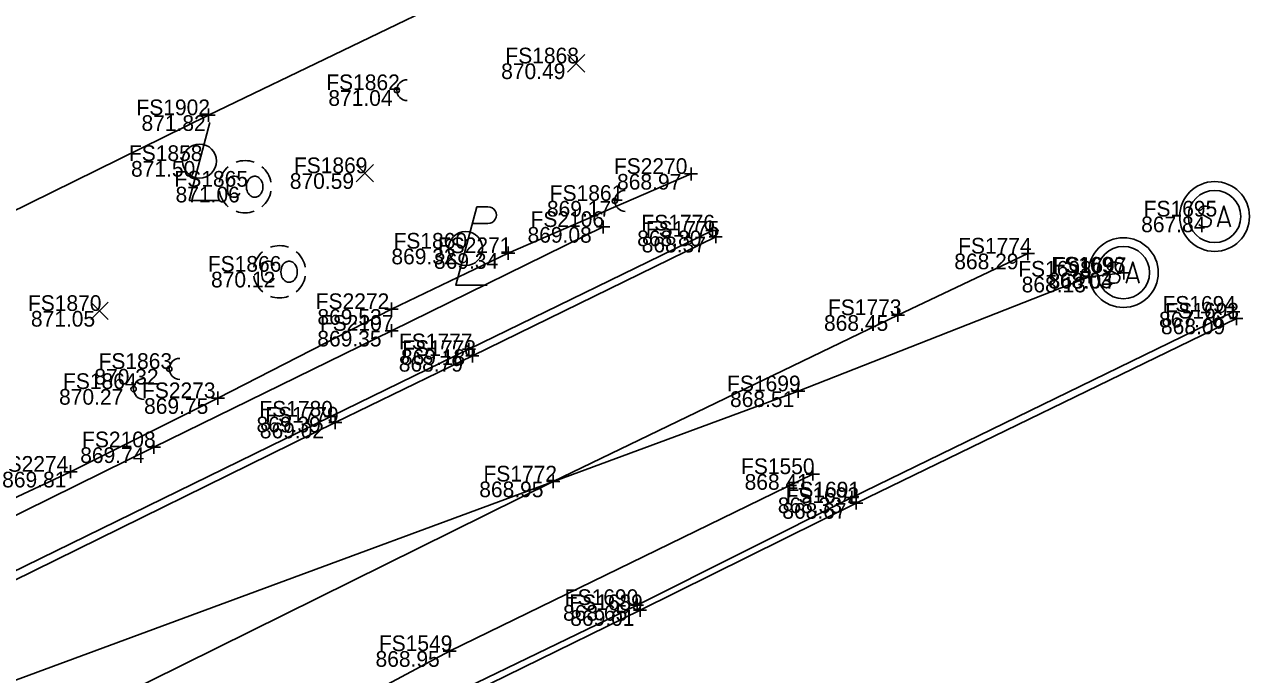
# Model space of a CAD drawing. Extents: x 1479420 to 1479833, y 379731 to 380103.
# Drawn here: x 1479739 to 1479832.6, y 379969.5 to 380019.2 of the extents above; entities that cross this region are included whole.
import ezdxf

# ---------------------------------------------------------------- set-up
doc = ezdxf.new("R2010")
doc.units = 0
for name, color, linetype in [('DR_X_Cells', 7, 'Continuous'), ('GK_Drainage_Nodes', 7, 'Continuous'), ('LT_X_Poles', 7, 'Continuous'), ('PM_X_CL_Double_Solid', 7, 'Continuous'), ('PV_X_Curb', 7, 'Continuous'), ('PV_X_Walk', 7, 'Continuous'), ('SV_X_Random_Point', 7, 'Continuous'), ('SV_X_Shot_Marker', 7, 'Continuous'), ('SV_X_Text_Elevation', 7, 'Continuous'), ('SV_X_Text_Name', 7, 'Continuous'), ('UT_X_Gas', 7, 'Continuous'), ('UT_X_Misc_Cells', 7, 'Continuous'), ('UT_X_Sanitary_Cells', 7, 'Continuous'), ('UT_X_Sanitary_Line', 7, 'Continuous'), ('UT_X_Water', 7, 'Continuous')]:
    doc.layers.add(name, color=color, linetype=linetype)

msp = doc.modelspace()

# ---------------------------------------------------------------- linework, layer by layer
at = {"layer": 'DR_X_Cells'}
for p, q in [((1479755.88, 380006.812), (1479755.88, 380006.812)), ((1479758.507, 380000.311), (1479758.507, 380000.311))]:
    msp.add_line(p, q, dxfattribs=at)
for points in [[(1479755.466, 380007.297), (1479755.403, 380007.435), (1479755.34, 380007.511), (1479755.277, 380007.561), (1479755.226, 380007.587), (1479755.088, 380007.612), (1479754.949, 380007.612), (1479754.773, 380007.561), (1479754.672, 380007.486), (1479754.621, 380007.423), (1479754.571, 380007.335), (1479754.533, 380007.196), (1479754.521, 380006.944), (1479754.521, 380006.755), (1479754.521, 380006.629), (1479754.533, 380006.516), (1479754.571, 380006.314), (1479754.584, 380006.276), (1479754.634, 380006.188), (1479754.685, 380006.125), (1479754.773, 380006.062), (1479754.848, 380006.037), (1479754.949, 380006.012), (1479755.062, 380006.012), (1479755.176, 380006.024), (1479755.214, 380006.037), (1479755.264, 380006.062), (1479755.314, 380006.113), (1479755.377, 380006.176), (1479755.428, 380006.251), (1479755.466, 380006.314)], [(1479756.486, 380007.599), (1479756.448, 380007.587), (1479756.41, 380007.574), (1479756.347, 380007.536), (1479756.31, 380007.511), (1479756.247, 380007.461), (1479756.196, 380007.41), (1479756.171, 380007.385), (1479756.133, 380007.335), (1479756.07, 380007.209), (1479756.02, 380007.083), (1479755.995, 380006.969), (1479755.982, 380006.805), (1479755.995, 380006.629), (1479756.032, 380006.503), (1479756.07, 380006.402), (1479756.095, 380006.352), (1479756.133, 380006.289), (1479756.184, 380006.226), (1479756.221, 380006.188), (1479756.259, 380006.15), (1479756.31, 380006.113), (1479756.373, 380006.075), (1479756.486, 380006.024), (1479756.549, 380006.012), (1479756.675, 380006.012), (1479756.725, 380006.024), (1479756.776, 380006.037), (1479756.839, 380006.062), (1479756.902, 380006.1), (1479756.939, 380006.125), (1479756.977, 380006.15), (1479757.015, 380006.188), (1479757.053, 380006.238), (1479757.078, 380006.276), (1479757.103, 380006.314), (1479757.128, 380006.352), (1479757.166, 380006.428), (1479757.204, 380006.516), (1479757.229, 380006.616), (1479757.242, 380006.705), (1479757.242, 380006.717), (1479757.242, 380006.805), (1479757.242, 380006.881), (1479757.229, 380006.982), (1479757.204, 380007.083), (1479757.179, 380007.158), (1479757.141, 380007.246), (1479757.103, 380007.322), (1479757.04, 380007.397), (1479756.99, 380007.448), (1479756.939, 380007.498), (1479756.889, 380007.536), (1479756.813, 380007.574), (1479756.738, 380007.599), (1479756.662, 380007.612), (1479756.574, 380007.612), (1479756.486, 380007.599)], [(1479758.093, 380000.796), (1479758.03, 380000.934), (1479757.967, 380001.01), (1479757.904, 380001.06), (1479757.853, 380001.085), (1479757.715, 380001.111), (1479757.576, 380001.111), (1479757.4, 380001.06), (1479757.299, 380000.985), (1479757.248, 380000.922), (1479757.198, 380000.833), (1479757.16, 380000.695), (1479757.148, 380000.443), (1479757.148, 380000.254), (1479757.148, 380000.128), (1479757.16, 380000.015), (1479757.198, 379999.813), (1479757.211, 379999.775), (1479757.261, 379999.687), (1479757.312, 379999.624), (1479757.4, 379999.561), (1479757.475, 379999.536), (1479757.576, 379999.511), (1479757.689, 379999.511), (1479757.803, 379999.523), (1479757.841, 379999.536), (1479757.891, 379999.561), (1479757.941, 379999.611), (1479758.004, 379999.674), (1479758.055, 379999.75), (1479758.093, 379999.813)], [(1479759.113, 380001.098), (1479759.075, 380001.085), (1479759.037, 380001.073), (1479758.974, 380001.035), (1479758.937, 380001.01), (1479758.874, 380000.959), (1479758.823, 380000.909), (1479758.798, 380000.884), (1479758.76, 380000.833), (1479758.697, 380000.707), (1479758.647, 380000.582), (1479758.622, 380000.468), (1479758.609, 380000.304), (1479758.622, 380000.128), (1479758.659, 380000.002), (1479758.697, 379999.901), (1479758.722, 379999.851), (1479758.76, 379999.788), (1479758.811, 379999.725), (1479758.848, 379999.687), (1479758.886, 379999.649), (1479758.937, 379999.611), (1479759, 379999.574), (1479759.113, 379999.523), (1479759.176, 379999.511), (1479759.302, 379999.511), (1479759.352, 379999.523), (1479759.403, 379999.536), (1479759.466, 379999.561), (1479759.529, 379999.599), (1479759.566, 379999.624), (1479759.604, 379999.649), (1479759.642, 379999.687), (1479759.68, 379999.737), (1479759.705, 379999.775), (1479759.73, 379999.813), (1479759.755, 379999.851), (1479759.793, 379999.926), (1479759.831, 380000.015), (1479759.856, 380000.115), (1479759.869, 380000.204), (1479759.869, 380000.216), (1479759.869, 380000.304), (1479759.869, 380000.38), (1479759.856, 380000.481), (1479759.831, 380000.582), (1479759.806, 380000.657), (1479759.768, 380000.745), (1479759.73, 380000.821), (1479759.667, 380000.896), (1479759.617, 380000.947), (1479759.566, 380000.997), (1479759.516, 380001.035), (1479759.44, 380001.073), (1479759.365, 380001.098), (1479759.289, 380001.111), (1479759.201, 380001.111), (1479759.113, 380001.098)]]:
    msp.add_lwpolyline(points, dxfattribs=at)
for centre, start, end in [((1479755.879, 380006.81), 70.05767, 110.10608), ((1479755.879, 380006.81), 130.0806, 170.07213), ((1479755.879, 380006.81), 10.01689, 50.03919), ((1479755.879, 380006.81), 190.01689, 230.03919), ((1479755.879, 380006.81), 310.01144, 350.02638), ((1479755.879, 380006.81), 250.05767, 290.04731), ((1479758.506, 380000.309), 70.05767, 110.10608), ((1479758.506, 380000.309), 130.0806, 170.07213), ((1479758.506, 380000.309), 10.01689, 50.03919), ((1479758.506, 380000.309), 190.01689, 230.03919), ((1479758.506, 380000.309), 310.01144, 350.02638), ((1479758.506, 380000.309), 250.05767, 290.04731)]:
    msp.add_arc(centre, 2, start, end, dxfattribs=at)
at = {"layer": 'GK_Drainage_Nodes'}
for p, q in [((1479829.977, 380006.534), (1479829.977, 380006.534)), ((1479829.977, 380004.534), (1479829.977, 380004.534)), ((1479829.977, 380004.534), (1479829.977, 380004.534)), ((1479829.977, 380004.534), (1479829.977, 380004.534)), ((1479823.004, 380002.243), (1479823.004, 380002.243)), ((1479829.977, 380002.534), (1479829.977, 380002.534)), ((1479823.004, 380000.243), (1479823.004, 380000.243)), ((1479823.004, 380000.243), (1479823.004, 380000.243)), ((1479823.004, 380000.243), (1479823.004, 380000.243)), ((1479823.004, 379998.243), (1479823.004, 379998.243))]:
    msp.add_line(p, q, dxfattribs=at)
for centre in [(1479829.977, 380004.534), (1479823.004, 380000.243)]:
    msp.add_circle(centre, 2, dxfattribs=at)
at = {"layer": 'LT_X_Poles'}
msp.add_lwpolyline([(1479753.18, 380011.73), (1479751.605, 380005.745), (1479753.968, 380005.745)], dxfattribs=at)
msp.add_circle((1479752.393, 380008.776), 1.3, dxfattribs=at)
at = {"layer": 'PM_X_CL_Double_Solid'}
msp.add_lwpolyline([(1479687.377, 379938.814), (1479706.5, 379948.023), (1479725.914, 379957.781), (1479746.012, 379967.724), (1479779.432, 379984.272), (1479805.773, 379996.992), (1479815.711, 380001.699)], dxfattribs=at)
at = {"layer": 'PV_X_Curb'}
for points in [[(1479795.994, 380033.189), (1479773.609, 380022.189), (1479753.08, 380012.28), (1479732.582, 380002.187), (1479709.578, 379990.944), (1479686.038, 379979.568), (1479675.424, 379995.638), (1479673.845, 379997.042), (1479672.388, 379997.402), (1479671.072, 379997.477), (1479668.749, 379997.507), (1479666.577, 379997.444), (1479665.261, 379997.435), (1479663.761, 379996.907), (1479662.621, 379996.118), (1479646.813, 379979.589), (1479631.39, 379994.413), (1479612.948, 380012.393), (1479594.615, 380030.048), (1479574.047, 380049.976), (1479559.355, 380064.639), (1479550.33, 380073.358), (1479530.481, 380092.839), (1479523.351, 380099.687)], [(1479791.848, 380002.989), (1479773.254, 379993.873), (1479762.766, 379988.772), (1479738.122, 379976.643), (1479720.845, 379968.214), (1479698.694, 379957.239), (1479678.815, 379947.539), (1479674.951, 379945.56), (1479671.194, 379943.855), (1479668.836, 379942.929), (1479666.481, 379942.243), (1479664.295, 379941.704), (1479662.026, 379941.397), (1479659.994, 379941.512), (1479654.023, 379942.767), (1479648.758, 379945.101), (1479643.81, 379948.553), (1479642.638, 379949.516), (1479640.65, 379951.389), (1479638.379, 379953.495), (1479620.029, 379971.274), (1479601.931, 379988.801), (1479602.178, 379989.373), (1479582.142, 380008.015)], [(1479791.59, 380003.464), (1479772.982, 379994.381), (1479762.438, 379989.23), (1479737.891, 379977.225), (1479720.638, 379968.611), (1479698.71, 379957.883), (1479678.409, 379947.915), (1479674.816, 379946.157), (1479670.835, 379944.353), (1479668.74, 379943.532), (1479666.343, 379942.649), (1479664.179, 379942.195), (1479661.876, 379941.9), (1479659.999, 379941.971), (1479653.935, 379943.268), (1479649.182, 379945.527), (1479644.261, 379948.889), (1479643.432, 379949.993), (1479639.011, 379953.958), (1479638.818, 379953.848), (1479620.557, 379971.482), (1479582.44, 380008.391)], [(1479695.142, 379911.53), (1479695.083, 379915.321), (1479695.466, 379917.321), (1479696.046, 379920.608), (1479697.317, 379923.298), (1479700.059, 379927.556), (1479702.833, 379930.769), (1479705.862, 379933.571), (1479707.032, 379934.346), (1479708.061, 379934.876), (1479711.183, 379937.553), (1479719.99, 379942.117), (1479736.739, 379950.532), (1479753.296, 379958.795), (1479766.716, 379965.563), (1479785.836, 379974.829), (1479802.25, 379983.054), (1479831.407, 379997.252)], [(1479764.96, 379957.314), (1479764.231, 379958.29), (1479763.83, 379960.018), (1479764.227, 379962.046), (1479765.13, 379963.344), (1479766.358, 379964.635), (1479767.372, 379965.186), (1479768.198, 379965.667), (1479786.067, 379974.436), (1479802.593, 379982.624), (1479831.64, 379996.732)]]:
    msp.add_lwpolyline(points, dxfattribs=at)
at = {"layer": 'PV_X_Walk'}
msp.add_lwpolyline([(1479783.245, 380003.732), (1479767.075, 379995.797), (1479748.905, 379986.887), (1479731.061, 379978.105)], dxfattribs=at)
at = {"layer": 'SV_X_Random_Point'}
for p, q in [((1479780.517, 380015.574), (1479781.851, 380016.909)), ((1479780.517, 380016.909), (1479781.851, 380015.574)), ((1479764.354, 380007.18), (1479765.688, 380008.515)), ((1479764.354, 380008.515), (1479765.688, 380007.18)), ((1479744.082, 379996.646), (1479745.416, 379997.981)), ((1479744.082, 379997.981), (1479745.416, 379996.646))]:
    msp.add_line(p, q, dxfattribs=at)
at = {"layer": 'SV_X_Shot_Marker'}
for p, q in [((1479753.08, 380012.78), (1479753.08, 380011.78)), ((1479752.58, 380012.28), (1479753.58, 380012.28)), ((1479753.08, 380012.28), (1479753.08, 380012.28)), ((1479789.966, 380008.289), (1479789.966, 380007.289)), ((1479789.466, 380007.789), (1479790.466, 380007.789)), ((1479789.966, 380007.789), (1479789.966, 380007.789)), ((1479783.245, 380004.232), (1479783.245, 380003.232)), ((1479782.745, 380003.732), (1479783.745, 380003.732)), ((1479783.245, 380003.732), (1479783.245, 380003.732)), ((1479791.09, 380003.464), (1479792.09, 380003.464)), ((1479791.59, 380003.964), (1479791.59, 380002.964)), ((1479791.59, 380003.464), (1479791.59, 380003.464)), ((1479791.848, 380003.489), (1479791.848, 380002.489)), ((1479791.348, 380002.989), (1479792.348, 380002.989)), ((1479791.848, 380002.989), (1479791.848, 380002.989)), ((1479775.482, 380001.733), (1479776.482, 380001.733)), ((1479775.982, 380002.233), (1479775.982, 380001.233)), ((1479775.982, 380001.733), (1479775.982, 380001.733)), ((1479815.211, 380001.699), (1479816.211, 380001.699)), ((1479815.711, 380002.199), (1479815.711, 380001.199)), ((1479815.711, 380001.699), (1479815.711, 380001.699)), ((1479820.4, 380000.433), (1479820.4, 379999.433)), ((1479823.042, 380000.72), (1479823.042, 379999.72)), ((1479819.9, 379999.933), (1479820.9, 379999.933)), ((1479820.4, 379999.933), (1479820.4, 379999.933)), ((1479822.542, 380000.22), (1479823.542, 380000.22)), ((1479823.042, 380000.22), (1479823.042, 380000.22)), ((1479767.065, 379997.956), (1479767.065, 379996.956)), ((1479831.407, 379997.752), (1479831.407, 379996.752)), ((1479766.565, 379997.456), (1479767.565, 379997.456)), ((1479767.065, 379997.456), (1479767.065, 379997.456)), ((1479805.273, 379996.992), (1479806.273, 379996.992)), ((1479805.773, 379997.492), (1479805.773, 379996.492)), ((1479805.773, 379996.992), (1479805.773, 379996.992)), ((1479830.907, 379997.252), (1479831.907, 379997.252)), ((1479831.14, 379996.732), (1479832.14, 379996.732)), ((1479831.407, 379997.252), (1479831.407, 379997.252)), ((1479831.64, 379997.232), (1479831.64, 379996.232)), ((1479831.64, 379996.732), (1479831.64, 379996.732)), ((1479766.575, 379995.797), (1479767.575, 379995.797)), ((1479767.075, 379996.297), (1479767.075, 379995.297)), ((1479767.075, 379995.797), (1479767.075, 379995.797)), ((1479772.982, 379994.881), (1479772.982, 379993.881)), ((1479772.482, 379994.381), (1479773.482, 379994.381)), ((1479772.754, 379993.873), (1479773.754, 379993.873)), ((1479772.982, 379994.381), (1479772.982, 379994.381)), ((1479773.254, 379994.373), (1479773.254, 379993.373)), ((1479773.254, 379993.873), (1479773.254, 379993.873)), ((1479753.798, 379991.143), (1479753.798, 379990.143)), ((1479797.647, 379991.168), (1479798.647, 379991.168)), ((1479798.147, 379991.668), (1479798.147, 379990.668)), ((1479798.147, 379991.168), (1479798.147, 379991.168)), ((1479753.298, 379990.643), (1479754.298, 379990.643)), ((1479753.798, 379990.643), (1479753.798, 379990.643)), ((1479761.938, 379989.23), (1479762.938, 379989.23)), ((1479762.438, 379989.73), (1479762.438, 379988.73)), ((1479762.438, 379989.23), (1479762.438, 379989.23)), ((1479762.766, 379989.272), (1479762.766, 379988.272)), ((1479762.266, 379988.772), (1479763.266, 379988.772)), ((1479762.766, 379988.772), (1479762.766, 379988.772)), ((1479748.905, 379987.387), (1479748.905, 379986.387)), ((1479748.405, 379986.887), (1479749.405, 379986.887)), ((1479748.905, 379986.887), (1479748.905, 379986.887)), ((1479742.535, 379985.518), (1479742.535, 379984.518)), ((1479742.035, 379985.018), (1479743.035, 379985.018)), ((1479742.535, 379985.018), (1479742.535, 379985.018)), ((1479779.432, 379984.772), (1479779.432, 379983.772)), ((1479798.77, 379984.838), (1479799.77, 379984.838)), ((1479799.27, 379985.338), (1479799.27, 379984.338)), ((1479799.27, 379984.838), (1479799.27, 379984.838)), ((1479778.932, 379984.272), (1479779.932, 379984.272)), ((1479779.432, 379984.272), (1479779.432, 379984.272)), ((1479802.25, 379983.554), (1479802.25, 379982.554)), ((1479801.75, 379983.054), (1479802.75, 379983.054)), ((1479802.093, 379982.624), (1479803.093, 379982.624)), ((1479802.25, 379983.054), (1479802.25, 379983.054)), ((1479802.593, 379983.124), (1479802.593, 379982.124)), ((1479802.593, 379982.624), (1479802.593, 379982.624)), ((1479785.836, 379975.329), (1479785.836, 379974.329)), ((1479785.336, 379974.829), (1479786.336, 379974.829)), ((1479785.567, 379974.436), (1479786.567, 379974.436)), ((1479785.836, 379974.829), (1479785.836, 379974.829)), ((1479786.067, 379974.936), (1479786.067, 379973.936)), ((1479786.067, 379974.436), (1479786.067, 379974.436)), ((1479771.505, 379971.804), (1479771.505, 379970.804)), ((1479771.005, 379971.304), (1479772.005, 379971.304)), ((1479771.505, 379971.304), (1479771.505, 379971.304))]:
    msp.add_line(p, q, dxfattribs=at)
at = {"layer": 'UT_X_Gas'}
msp.add_lwpolyline([(1479732.065, 379980.116), (1479742.535, 379985.018), (1479753.798, 379990.643), (1479767.065, 379997.456), (1479775.982, 380001.733), (1479789.966, 380007.789)], dxfattribs=at)
at = {"layer": 'UT_X_Misc_Cells'}
for p, q in [((1479773.586, 380005.278), (1479774.436, 380005.278)), ((1479773.244, 380004.003), (1479774.436, 380004.003))]:
    msp.add_line(p, q, dxfattribs=at)
msp.add_lwpolyline([(1479773.586, 380005.278), (1479771.979, 379999.278), (1479774.379, 379999.278)], dxfattribs=at)
for centre, radius in [((1479767.474, 380014.194), 0.2), ((1479784.13, 380005.729), 0.2), ((1479772.729, 380002.078), 1.3), ((1479750.081, 379992.882), 0.2), ((1479747.355, 379991.345), 0.2)]:
    msp.add_circle(centre, radius, dxfattribs=at)
for centre, radius, start, end in [((1479768.274, 380014.194), 0.8, 90, 270), ((1479784.93, 380005.729), 0.8, 90, 270), ((1479774.448, 380004.641), 0.638, 268.8767, 91.1233), ((1479750.881, 379992.882), 0.8, 90, 270), ((1479748.155, 379991.345), 0.8, 90, 270)]:
    msp.add_arc(centre, radius, start, end, dxfattribs=at)
at = {"layer": 'UT_X_Sanitary_Cells'}
for points in [[(1479829.644, 380005.22), (1479829.619, 380005.246), (1479829.581, 380005.271), (1479829.468, 380005.309), (1479829.329, 380005.334), (1479829.229, 380005.334), (1479829.191, 380005.334), (1479829.027, 380005.296), (1479828.889, 380005.22), (1479828.8, 380005.12), (1479828.775, 380005.019), (1479828.775, 380004.943), (1479828.8, 380004.843), (1479828.901, 380004.754), (1479829.594, 380004.376), (1479829.657, 380004.326), (1479829.682, 380004.276), (1479829.707, 380004.2), (1479829.707, 380004.125), (1479829.695, 380004.049), (1479829.682, 380003.999), (1479829.657, 380003.935), (1479829.632, 380003.885), (1479829.607, 380003.847), (1479829.569, 380003.81), (1479829.531, 380003.784), (1479829.481, 380003.759), (1479829.443, 380003.747), (1479829.329, 380003.734), (1479829.153, 380003.734), (1479829.04, 380003.759), (1479828.876, 380003.847), (1479828.775, 380003.923)], [(1479830.186, 380003.734), (1479830.69, 380005.334), (1479831.181, 380003.734)], [(1479831.055, 380004.112), (1479830.312, 380004.112)], [(1479822.671, 380000.929), (1479822.646, 380000.954), (1479822.608, 380000.98), (1479822.495, 380001.017), (1479822.356, 380001.043), (1479822.256, 380001.043), (1479822.218, 380001.043), (1479822.054, 380001.005), (1479821.916, 380000.929), (1479821.827, 380000.828), (1479821.802, 380000.728), (1479821.802, 380000.652), (1479821.827, 380000.551), (1479821.928, 380000.463), (1479822.621, 380000.085), (1479822.684, 380000.035), (1479822.709, 379999.984), (1479822.734, 379999.909), (1479822.734, 379999.833), (1479822.722, 379999.758), (1479822.709, 379999.707), (1479822.684, 379999.644), (1479822.659, 379999.594), (1479822.634, 379999.556), (1479822.596, 379999.518), (1479822.558, 379999.493), (1479822.508, 379999.468), (1479822.47, 379999.455), (1479822.356, 379999.443), (1479822.18, 379999.443), (1479822.067, 379999.468), (1479821.903, 379999.556), (1479821.802, 379999.632)], [(1479823.213, 379999.443), (1479823.717, 380001.043), (1479824.208, 379999.443)], [(1479824.082, 379999.821), (1479823.339, 379999.821)]]:
    msp.add_lwpolyline(points, dxfattribs=at)
for centre, radius in [((1479829.977, 380004.534), 2.667), ((1479829.977, 380004.534), 2), ((1479823.004, 380000.243), 2.667), ((1479823.004, 380000.243), 2)]:
    msp.add_circle(centre, radius, dxfattribs=at)
at = {"layer": 'UT_X_Sanitary_Line'}
msp.add_lwpolyline([(1479514.622, 379866.87), (1479542.109, 379880.195), (1479565.169, 379891.725), (1479588.442, 379902.577), (1479600.276, 379909.045), (1479620.421, 379921.063), (1479621.963, 379921.485), (1479624.647, 379923.417), (1479645.234, 379932.512), (1479652.585, 379935.616), (1479664.157, 379939.675), (1479679.103, 379944.837), (1479710.112, 379956.448), (1479736.037, 379968.233), (1479798.147, 379991.168), (1479820.4, 379999.933), (1479823.042, 380000.22)], dxfattribs=at)
at = {"layer": 'UT_X_Water'}
msp.add_lwpolyline([(1479653.917, 379883.075), (1479656.453, 379885.901), (1479682.649, 379913.582), (1479686.182, 379917.14), (1479686.736, 379917.656), (1479692.788, 379923.268), (1479699.703, 379929.77), (1479707.876, 379935.91), (1479714.6, 379939.488), (1479720.618, 379942.792), (1479734.686, 379951.003), (1479759.021, 379964.62), (1479771.505, 379971.304), (1479799.27, 379984.838)], dxfattribs=at)

# ---------------------------------------------------------------- texts
at = {"layer": 'SV_X_Text_Elevation'}
for s, p in [('870.49', (1479775.449, 380015.041)), ('871.04', (1479762.24, 380012.994)), ('871.82', (1479747.96, 380011.08)), ('871.50', (1479747.159, 380007.577)), ('870.59', (1479759.295, 380006.647)), ('868.97', (1479784.307, 380006.589)), ('871.06', (1479750.561, 380005.612)), ('869.17', (1479778.944, 380004.529)), ('867.84', (1479824.365, 380003.334)), ('869.08', (1479777.463, 380002.532)), ('868.80', (1479785.845, 380002.264)), ('868.37', (1479786.189, 380001.789)), ('869.32', (1479767.06, 380000.878)), ('869.34', (1479770.313, 380000.533)), ('868.29', (1479810.08, 380000.499)), ('870.12', (1479753.273, 379999.111)), ('868.13', (1479815.232, 379998.733)), ('868.03', (1479817.25, 379999.043)), ('868.04', (1479817.297, 379999.02)), ('871.05', (1479739.506, 379996.113)), ('869.53', (1479761.406, 379996.256)), ('868.45', (1479800.123, 379995.792)), ('867.76', (1479825.729, 379996.052)), ('868.09', (1479825.877, 379995.532)), ('869.35', (1479761.397, 379994.597)), ('868.79', (1479767.623, 379992.673)), ('869.18', (1479767.786, 379993.181)), ('870.32', (1479744.355, 379991.682)), ('870.27', (1479741.658, 379990.145)), ('868.51', (1479792.94, 379989.968)), ('869.75', (1479748.157, 379989.443)), ('869.39', (1479756.75, 379988.03)), ('869.02', (1479757.003, 379987.572)), ('869.74', (1479743.274, 379985.687)), ('869.81', (1479737.309, 379983.818)), ('868.41', (1479794.054, 379983.638)), ('868.95', (1479773.773, 379983.072)), ('868.33', (1479796.591, 379981.854)), ('868.67', (1479796.934, 379981.424)), ('868.65', (1479780.177, 379973.629)), ('869.01', (1479780.728, 379973.236)), ('868.95', (1479765.846, 379970.104))]:
    msp.add_text(s, height=1.2, dxfattribs=at).set_placement(p)
at = {"layer": 'SV_X_Text_Name'}
for s, p in [('FS1868', (1479775.771, 380016.241)), ('FS1862', (1479762.08, 380014.194)), ('FS1902', (1479747.572, 380012.28)), ('FS1858', (1479746.999, 380008.777)), ('FS1869', (1479759.608, 380007.847)), ('FS2270', (1479784.061, 380007.789)), ('FS1865', (1479750.476, 380006.812)), ('FS1861', (1479779.16, 380005.729)), ('FS1695', (1479824.554, 380004.534)), ('FS2106', (1479777.69, 380003.732)), ('FS1776', (1479786.167, 380003.464)), ('FS1775', (1479786.501, 380002.989)), ('FS1860', (1479767.221, 380002.078)), ('FS2271', (1479770.615, 380001.733)), ('FS1774', (1479810.373, 380001.699)), ('FS1866', (1479753.028, 380000.311)), ('FS1696', (1479817.506, 380000.243)), ('FS1697', (1479817.619, 380000.22)), ('FS1698', (1479814.968, 379999.933)), ('FS1870', (1479739.279, 379997.313)), ('FS2272', (1479761.273, 379997.456)), ('FS1773', (1479800.426, 379996.992)), ('FS1694', (1479825.994, 379997.252)), ('FS1693', (1479826.217, 379996.732)), ('FS2107', (1479761.596, 379995.797)), ('FS1777', (1479767.635, 379994.381)), ('FS1778', (1479767.898, 379993.873)), ('FS1863', (1479744.677, 379992.882)), ('FS1864', (1479741.961, 379991.345)), ('FS1699', (1479792.715, 379991.168)), ('FS2273', (1479747.997, 379990.643)), ('FS1780', (1479756.968, 379989.23)), ('FS1779', (1479757.41, 379988.772)), ('FS2108', (1479743.416, 379986.887)), ('FS2274', (1479736.743, 379985.018)), ('FS1772', (1479774.094, 379984.272)), ('FS1550', (1479793.781, 379984.838)), ('FS1692', (1479797.18, 379982.624)), ('FS1691', (1479797.261, 379983.054)), ('FS1690', (1479780.309, 379974.829)), ('FS1689', (1479780.654, 379974.436)), ('FS1549', (1479766.101, 379971.304))]:
    msp.add_text(s, height=1.2, dxfattribs=at).set_placement(p)

doc.saveas('drawing.dxf')
